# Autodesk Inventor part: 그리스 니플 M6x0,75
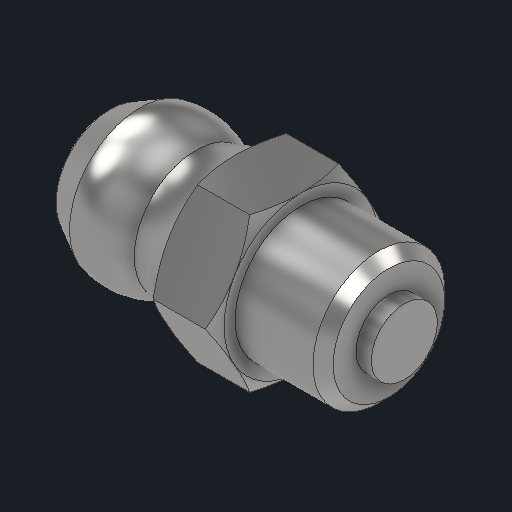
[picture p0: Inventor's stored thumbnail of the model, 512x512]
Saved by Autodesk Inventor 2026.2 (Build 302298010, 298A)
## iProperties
Created: 2026-03
Part Number: 그리스 니플 M6x0,75
Material: 강철, 연강
Description: 윤활 니플, 원추 유형 A
Document SubType Name: Modeling
Designer: PC2-02
Density: 7.85 g/cm^3
Appearance: 기본값
Author: jhkim
Sending System: Autodesk Inventor 2026
Preprocessor: ST-DEVELOPER v20.1
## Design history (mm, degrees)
feature "Solid1"
node "솔리드1"
